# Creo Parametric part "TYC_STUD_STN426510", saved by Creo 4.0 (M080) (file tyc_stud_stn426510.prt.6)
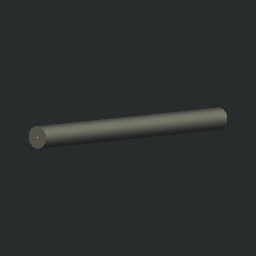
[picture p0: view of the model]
Units: Custom; MM, KILOGRAM, SECS
Materials in the file: OCEL_N

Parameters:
  NORMINFO = "Stabstahl Formstahl; Kaltgewalzter rundkantiger U-Stahl"
  KATEGORIE = "0"
  DESIGNER = "."
  DATE = "."
  FORMAT = "."
  MOD_INDEX_1 = "."
  MOD_INDEX_2 = "."
  MOD_INDEX_3 = "."
  MOD_INDEX_4 = "."
  MOD_INDEX_5 = "."
  MOD_INDEX_6 = "."
  MOD_INDEX_7 = "."
  MOD_INDEX_8 = "."
  MOD_NOTE_1 = "."
  MOD_NOTE_2 = "."
  MOD_NOTE_3 = "."
  MOD_NOTE_4 = "."
  MOD_NOTE_5 = "."
  MOD_NOTE_6 = "."
  MOD_NOTE_7 = "."
  MOD_NOTE_8 = "."
  MOD_DATE_1 = "."
  MOD_DATE_2 = "."
  MOD_DATE_3 = "."
  MOD_DATE_4 = "."
  MOD_DATE_5 = "."
  MOD_DATE_6 = "."
  MOD_DATE_7 = "."
  MOD_DATE_8 = "."
  MOD_NAME_1 = "."
  MOD_NAME_2 = "."
  MOD_NAME_3 = "."
  MOD_NAME_4 = "."
  MOD_NAME_5 = "."
  MOD_NAME_6 = "."
  MOD_NAME_7 = "."
  MOD_NAME_8 = "."
  HERSTELLER = "."
  ZEICHNUNGSNUMMER = "."
  NAZOV = "TYC_STUD_STN426510"
  ROZMER = "KR 8h9x100"
  NORMA = "STN 42 6510"
  MATERIAL_ZAKL = "."
  HMOTNOST_HR = "."
  PTC_MATERIAL_NAME = "OCEL_N"

Other parameters: L, QUERSCHNITT, HMOTNOST, HUSTOTA, HMOTNOST_1, D24

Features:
  1. datum plane "Y-Y"
  2. datum plane "X-X"
  3. datum plane "Z-Z"
  4. coordinate system
  5. datum axis
  6. datum axis
  7. datum axis
  8. protrusion
  9. datum point "PNT0"
  10. datum point "PNT1"
  11. curve

Other named items: ZZ, XX, YY, CS0

Named dimensions: Laenge, laenge_nf

Layers: BEZUG, BEZUGSACHSEN, KONSTRUKTIONSELEMENTE, PLAZIERUNG, PROFIL_NEUTRALE_FASER

Notes: Rundstahl | Rund 8x100 | DxL 8x100 | Gewicht:  | 0.087 | Querschnittsfläche: A=  | 0.503 |  cm²

Family table entries: GENERIC, TYC_KR_2, TYC_STUD_STN426510, value(d_val), value(s_val), value(i_val), TYC_KR_2_5, TYC_STUD_STN426510, TYC_KR_3, TYC_STUD_STN426510, TYC_KR_3_5, TYC_STUD_STN426510, TYC_KR_4, TYC_STUD_STN426510, TYC_KR_4_5, TYC_STUD_STN426510, TYC_KR_5, TYC_STUD_STN426510, TYC_KR_5_5, TYC_STUD_STN426510, TYC_KR_6, TYC_STUD_STN426510, TYC_KR_7, TYC_STUD_STN426510, TYC_KR_8, TYC_STUD_STN426510, !/ , TYC_KR_10, TYC_STUD_STN426510, !/$, TYC_KR_12, TYC_STUD_STN426510, !/(, TYC_KR_13, TYC_STUD_STN426510, !/*, TYC_KR_14, TYC_STUD_STN426510, !/,, TYC_KR_15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

Surfaces: 2 plane, 1 cylinder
